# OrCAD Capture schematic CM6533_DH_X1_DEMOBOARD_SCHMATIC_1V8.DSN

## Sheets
1 00. Note: title: Note; rev: 1.8; company: C-MEDIA ELECTRONICS Inc.; note: CM6533_DH_X1_DEMOBOARD_SCHMATIC; note: 6F., 100, Sec. 4, Civil Boulevard, Taipei, Taiwan, R.O.C.
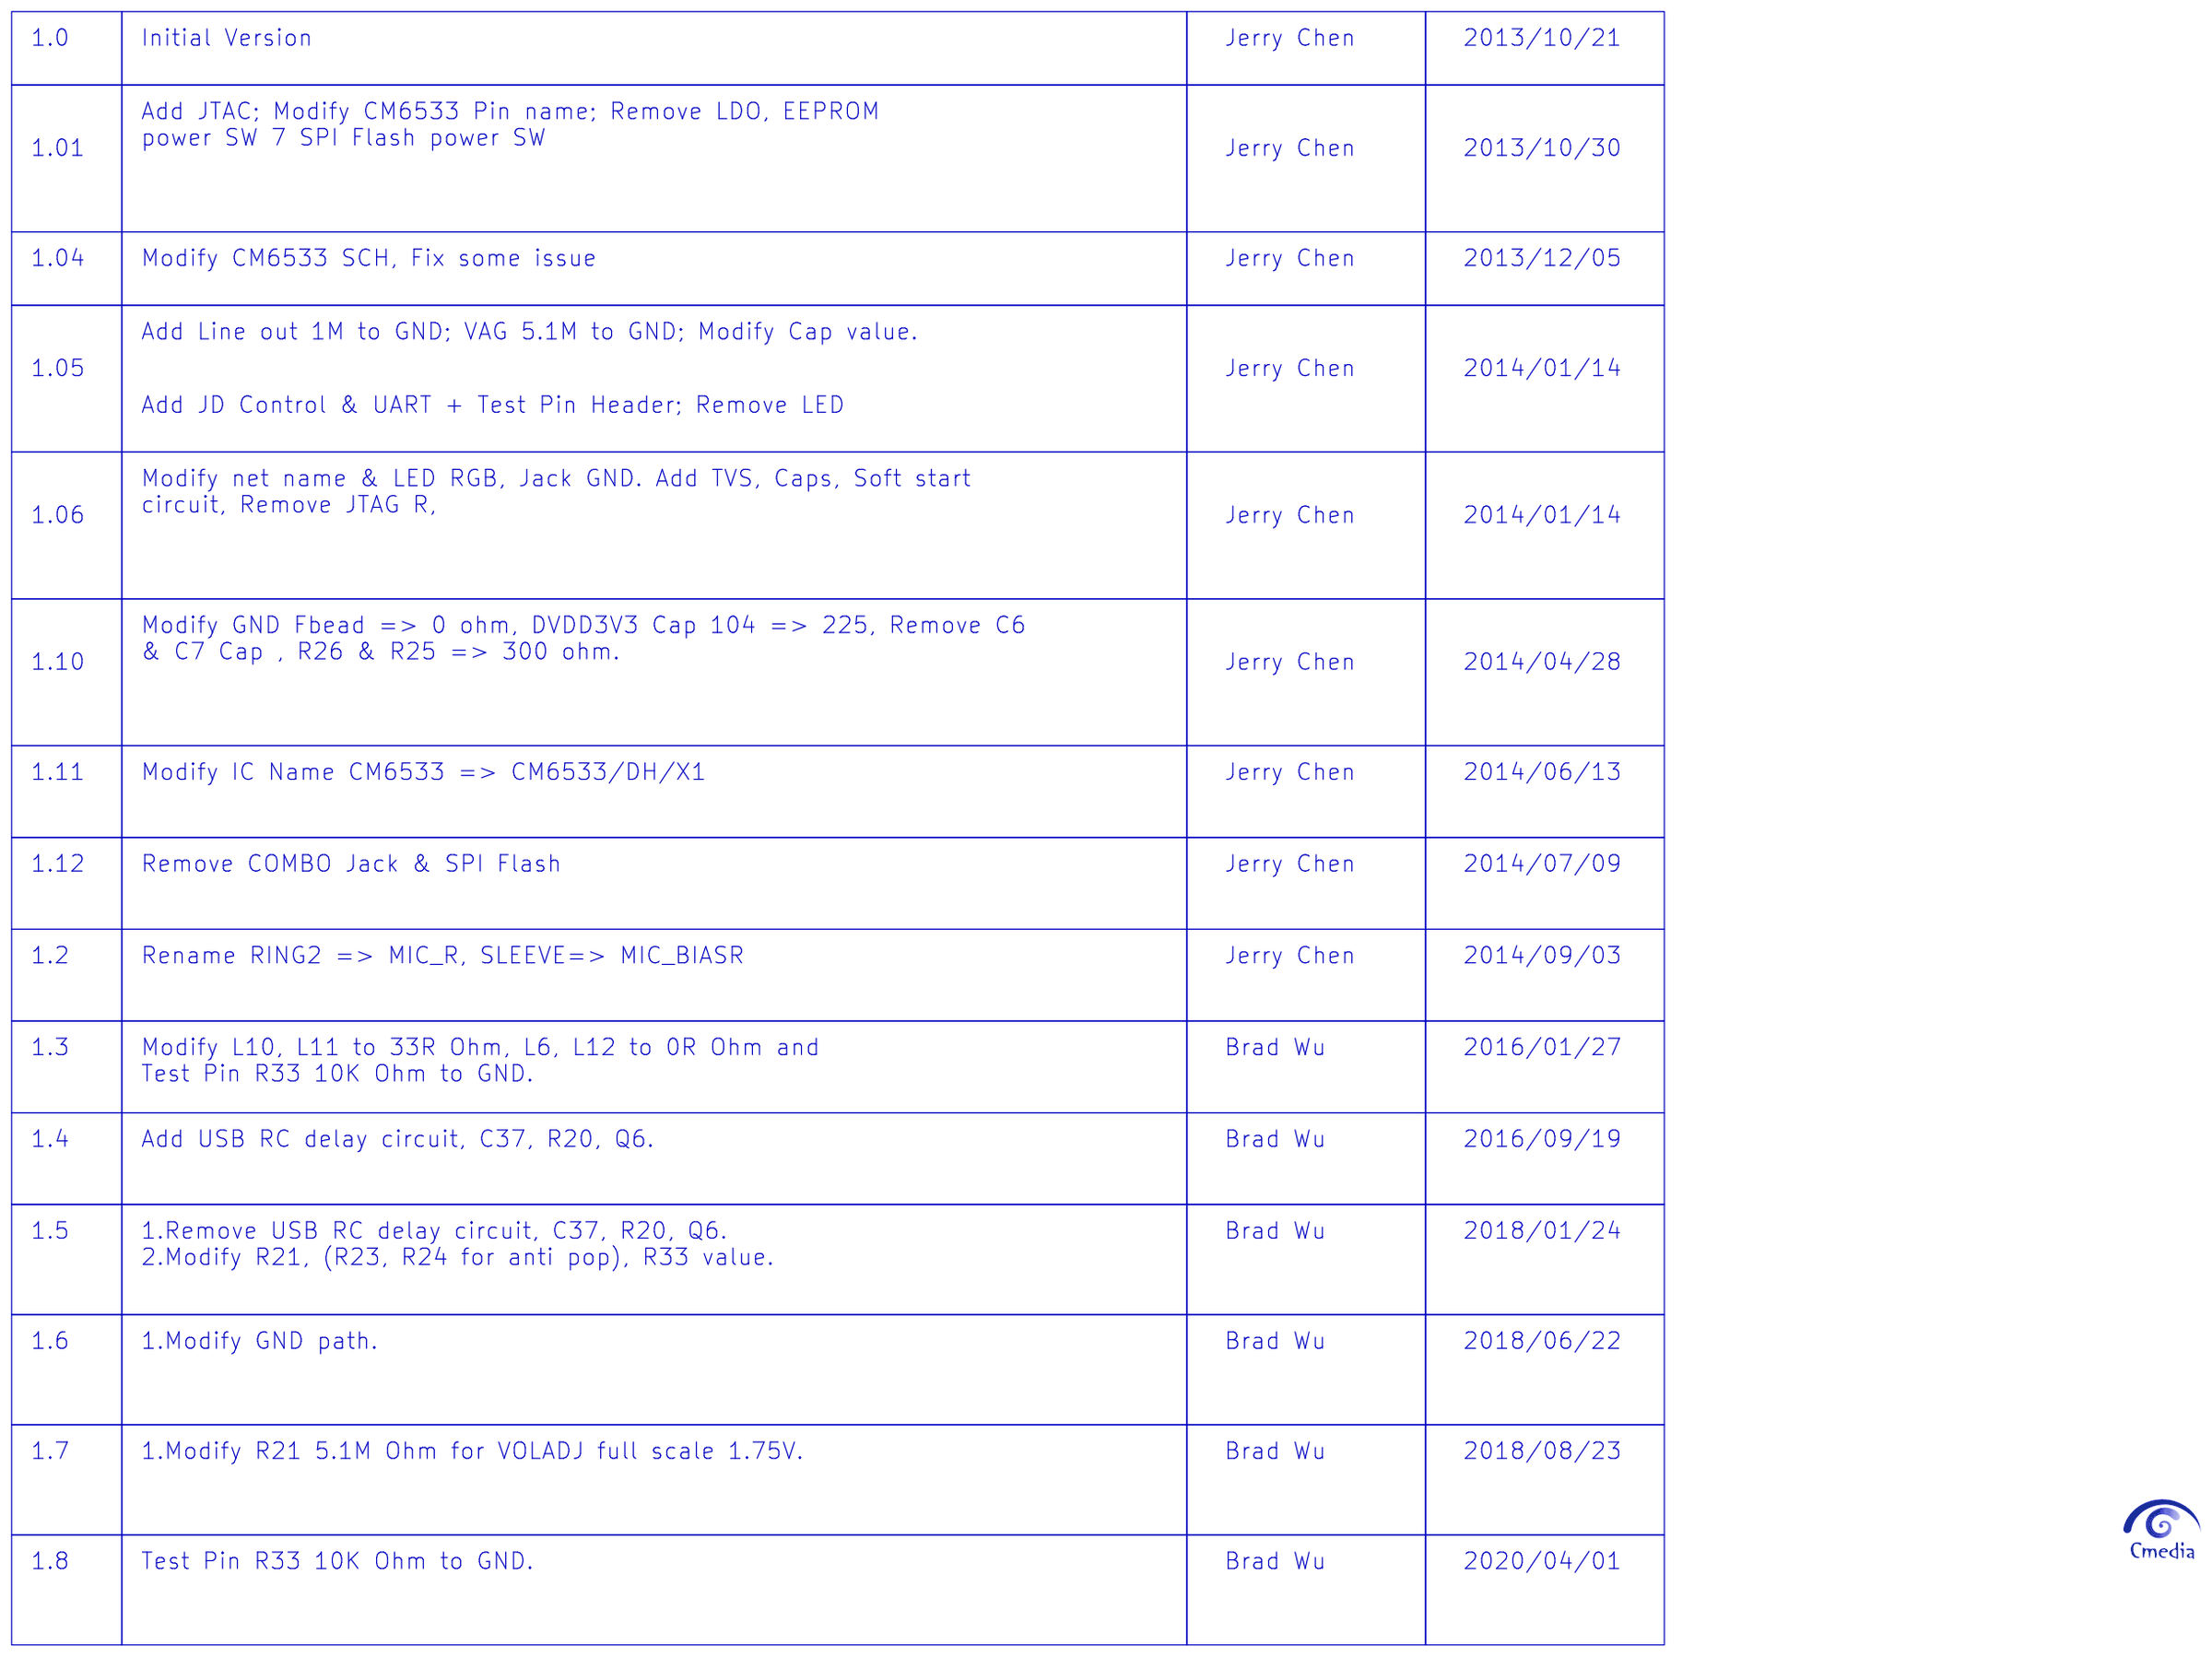
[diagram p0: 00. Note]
2 01. Placement: title: Placement
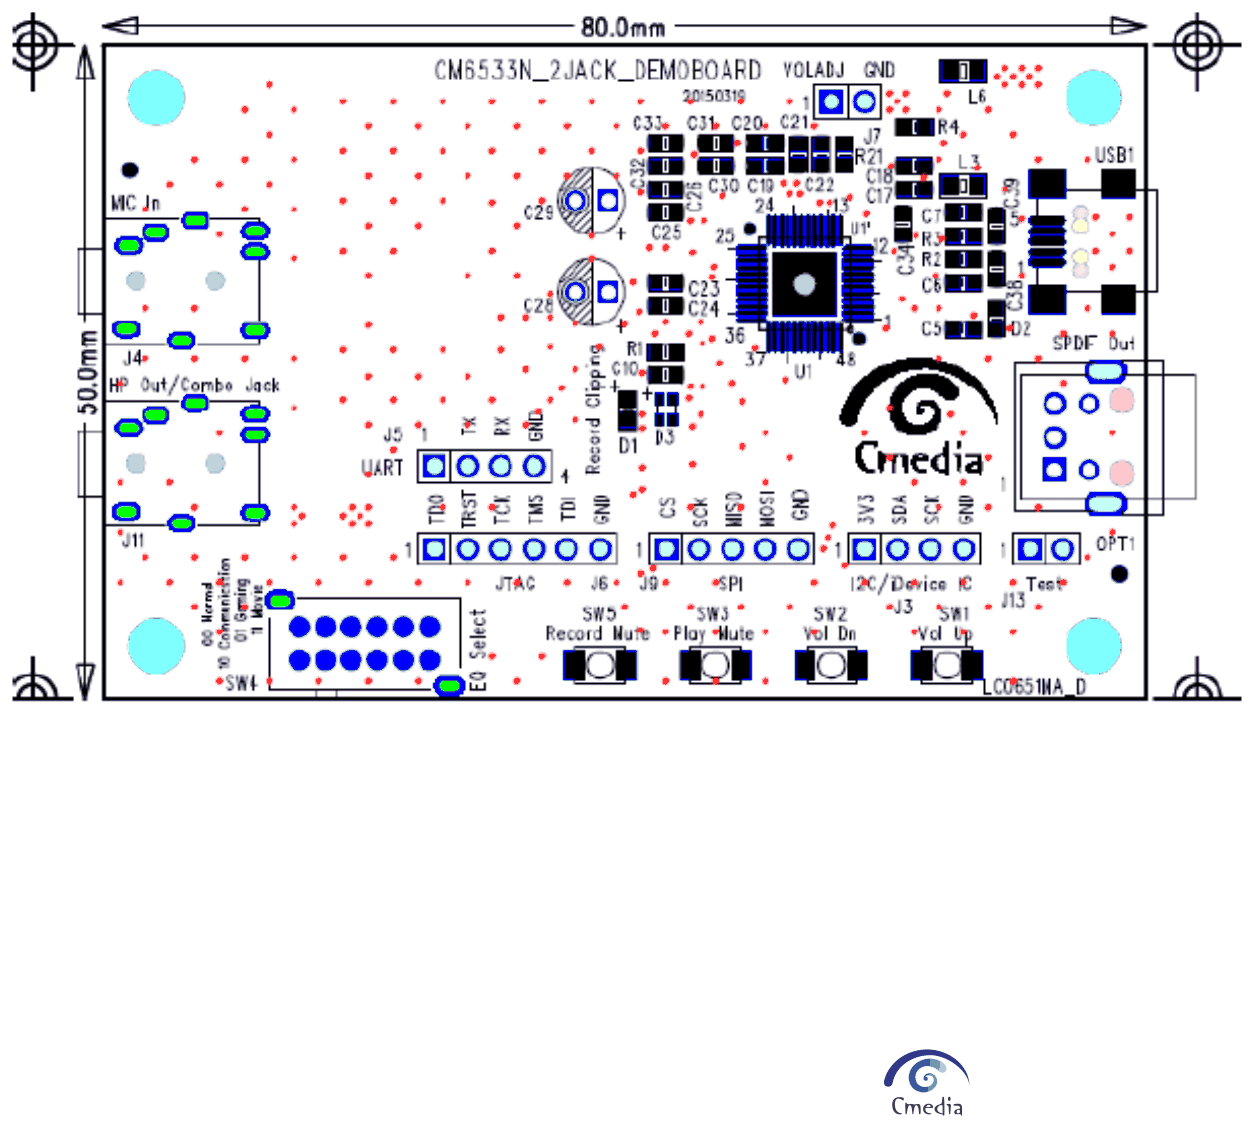
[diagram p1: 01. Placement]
3 02. Block: title: BLOCK
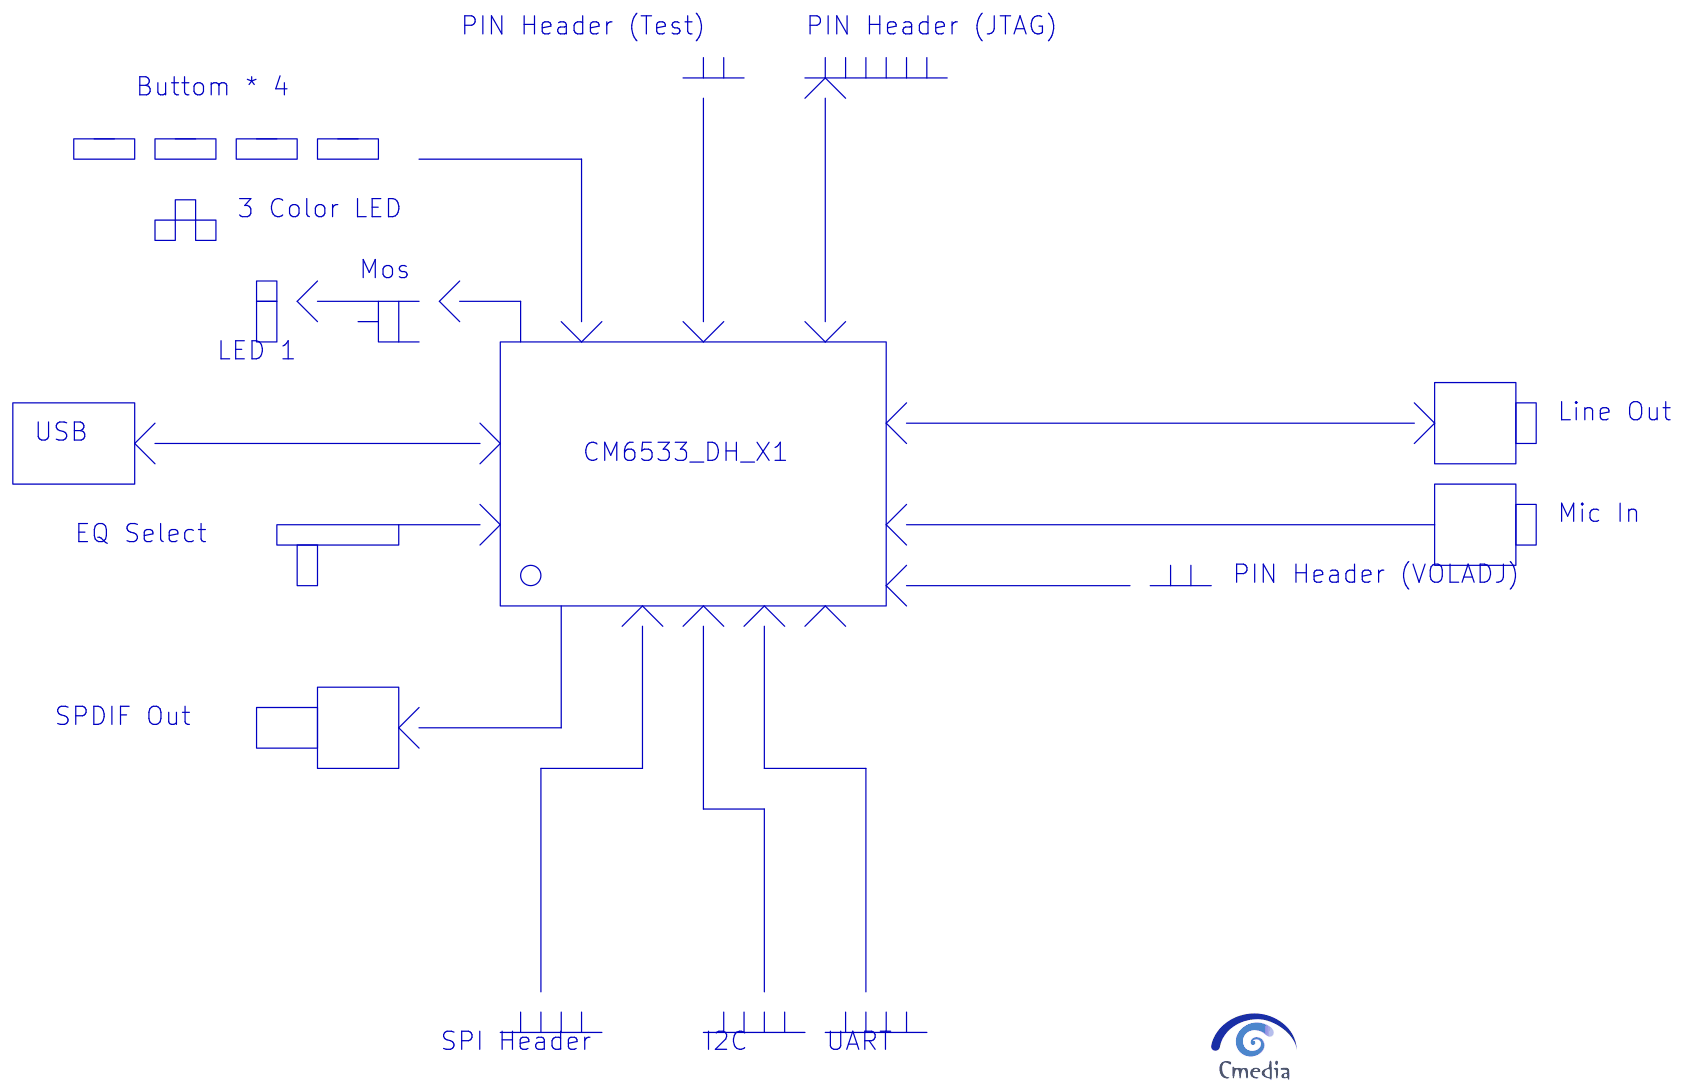
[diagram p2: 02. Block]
4 03. CM6533 Main: size B; title: CM6533/DH/X1 Demoboard
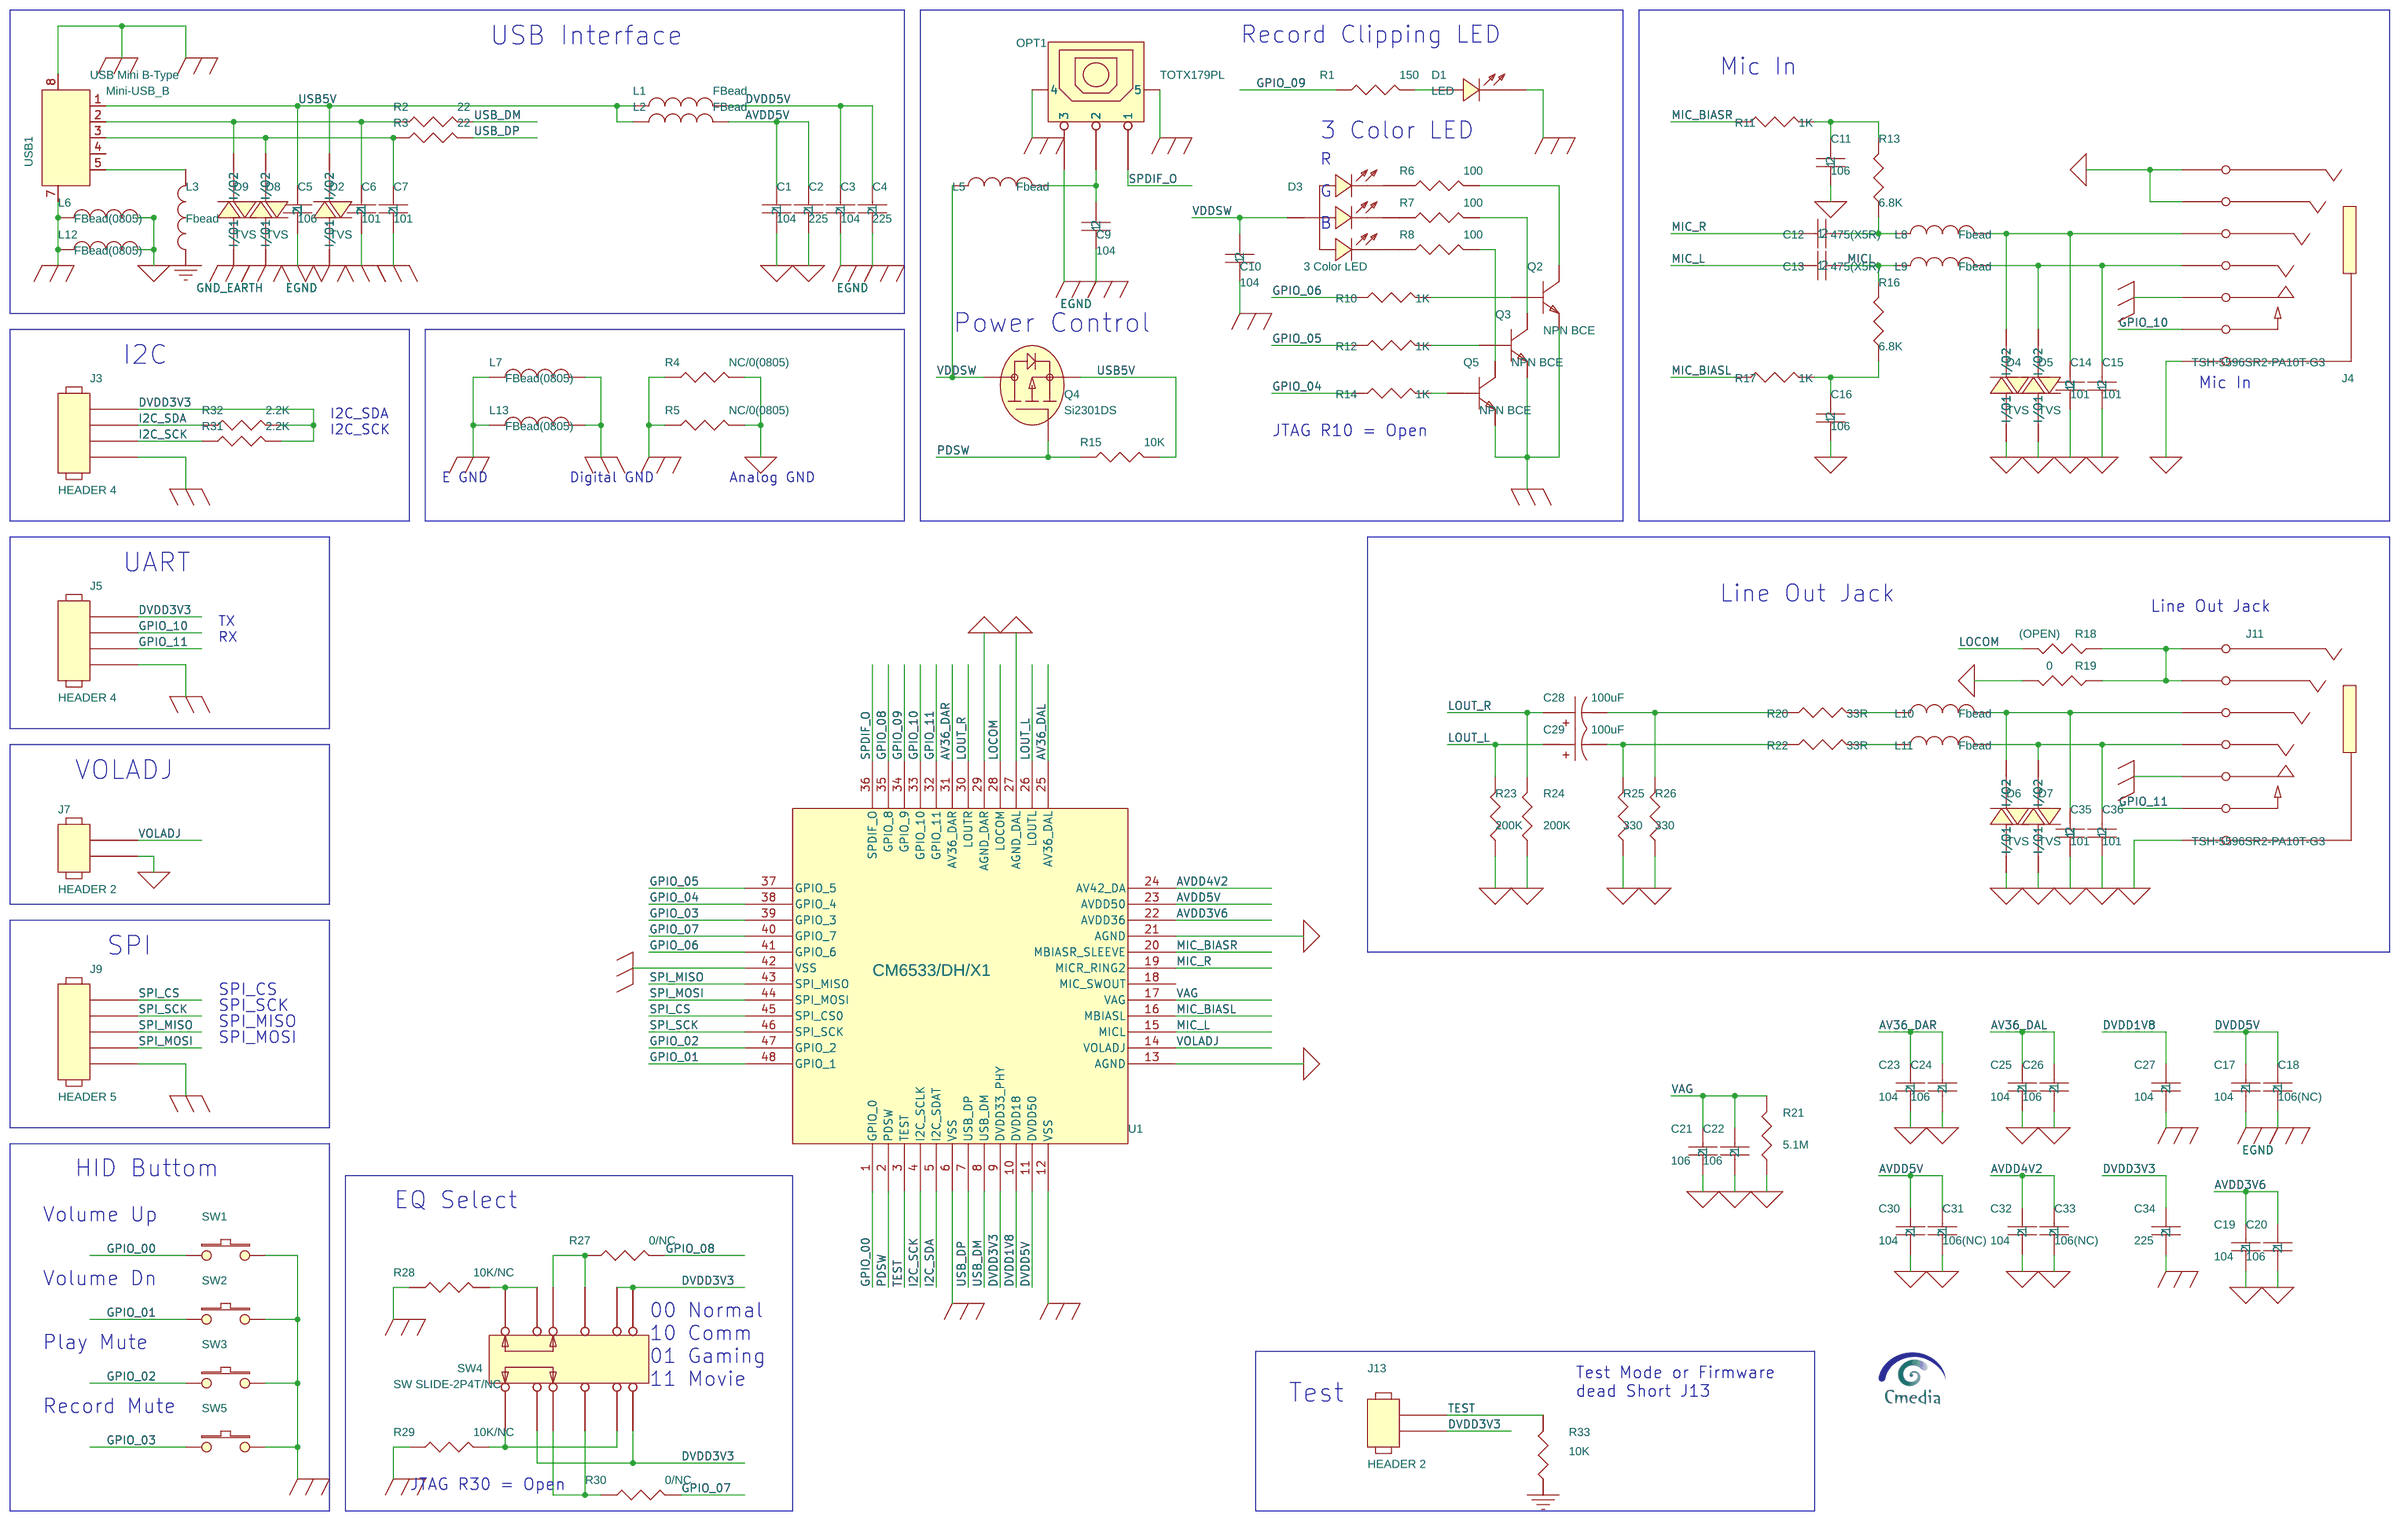
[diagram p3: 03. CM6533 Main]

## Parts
C1  104
C2  225
C3  104
C4  225
C5  106
C6  101
C7  101
C9  104
C10  104  [SM/C_0603]
C11  106
C12  475(X5R)
C13  475(X5R)
C14  101
C15  101
C16  106
C17  104
C18  106(NC)
C19  104
C20  106
C21  106
C22  106
C23  104
C24  106
C25  104
C26  106
C27  104
C28  100uF
C29  100uF
C30  104
C31  106(NC)
C32  104
C33  106(NC)
C34  225
C35  101
C36  101
D1  LED
D2  TVS
D3  3 Color LED
D4  TVS
D5  TVS
D6  TVS
D7  TVS
D8  TVS
D9  TVS
J3  HEADER 4
J4  TSH-5596SR2-PA10T-G3  [DIP]
J5  HEADER 4
J7  HEADER 2
J9  HEADER 5
J11  TSH-5596SR2-PA10T-G3  [DIP]
J13  HEADER 2
L1  FBead
L2  FBead
L3  Fbead
L5  Fbead
L6  FBead(0805)  [L0805]
L7  FBead(0805)  [L0805]
L8  Fbead
L9  Fbead
L10  Fbead
L11  Fbead
L12  FBead(0805)  [L0805]
L13  FBead(0805)  [L0805]
OPT1  TOTX179PL
Q2  NPN BCE
Q3  NPN BCE
Q4  Si2301DS  [SOT23]
Q5  NPN BCE
R1  150
R2  22
R3  22
R4  NC/0(0805)
R5  NC/0(0805)
R6  100  [R0603]
R7  100  [R0603]
R8  100  [R0603]
R10  1K
R11  1K
R12  1K
R13  6.8K
R14  1K
R15  10K  [R0603]
R16  6.8K
R17  1K
R18  (OPEN)
R19  0
R20  33R
R21  5.1M
R22  33R
R23  200K
R24  200K
R25  330
R26  330
R27  0/NC
R28  10K/NC
R29  10K/NC
R30  0/NC
R31  2.2K
R32  2.2K
R33  10K  [R0603]
SW1  CTT-1135  [TACKSW2-150]
SW2  CTT-1135  [TACKSW2-150]
SW3  CTT-1135  [TACKSW2-150]
SW4  SW SLIDE-2P4T/NC
SW5  CTT-1135  [TACKSW2-150]
U1  CM6533/DH/X1
USB1  Mini-USB_B  [USB-TYPEB-SMD]

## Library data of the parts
C1 = CAP_NP_13
C2 = CAP_NP_7
C3 = CAP_NP_11
C4 = CAP_NP_30
C5 = CAP_NP_15
C6 = CAP_NP_27
C7 = CAP_NP_9
C9 = CAP_NP_19
C10 = CAP_NP_5
C11 = CAP_NP_24
C12 = CAP_NP_18
C13 = CAP_NP_26
C14 = CAP_NP_16
C15 = CAP_NP
C16 = CAP_NP_17
C17 = CAP_NP_12
C18 = CAP_NP_28
C19 = CAP_NP_22
C20 = CAP_NP_6
C21 = CAP_NP_23
C22 = CAP_NP_25
C23 = CAP_NP_29
C24 = CAP_NP_14
C25 = CAP_NP_8
C26 = CAP_NP_31
C27 = CAP_NP_3
C28 C29 = CAPACITOR_POL
C30 = CAP_NP_20
C31 = CAP_NP_1
C32 = CAP_NP_21
C33 = CAP_NP_2
C34 = CAP_NP_4
C35 = CAP_NP_32
C36 = CAP_NP_10
D1 = LED
D2 D4-D9 = DA108S1_SO_2
D3 = LED_3
J3 J5 = HEADER_5_3
J4 J11 = PHONEJACK_STEREO_SW_15
J7 J13 = HEADER_5_5
J9 = HEADER_5_7
L1 = INDUCTOR_9
L2 = INDUCTOR_10
L3 = INDUCTOR_6
L5 = INDUCTOR_7
L6 = INDUCTOR_1
L7 = INDUCTOR_2
L8 = INDUCTOR
L9 = INDUCTOR_5
L10 = INDUCTOR_8
L11 = INDUCTOR_3
L12 = INDUCTOR_11
L13 = INDUCTOR_4
OPT1 = HEADER_3_2: 1ST PART FIELD: TOTX178
Q2 Q3 Q5 = NPN_BCE
Q4 = PWRMOSFET_EP_GSD_2
R1-R8 R10-R33 = R
SW1-SW3 SW5 = SW_PUSHBUTTON: 1ST PART FIELD: WAKE UP
SW4 = SW_SLIDE-4P2T_0
U1 = CMI120_22
USB1 = HEADER_4_2: 1ST PART FIELD: USB Mini B-Type

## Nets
AGND: C1.2 C2.2 C11.1 C14.1 C15.1 C16.1 C19.2 C20.2 C21.2 C22.2 C23.2 C24.2 C25.2 C26.2 C30.2 C31.2 C32.2 C33.2 C35.1 C36.1 D4.1(I/O1) D5.1(I/O1) D6.1(I/O1) D7.1(I/O1) J4.3 J4.4 J4.7 J7.2 J11.7 L6.2 L12.2 R4.2 R5.2 R19.1 R21.1 R23.1 R24.1 R25.1 R26.1 U1.13(AGND) U1.21(AGND) U1.27(AGND_DAL) U1.29(AGND_DAR)
AV36_DAL: C25.1 C26.1 U1.25(AV36_DAL)
AV36_DAR: C23.1 C24.1 U1.31(AV36_DAR)
AVDD3V6: C19.1 C20.1 U1.22(AVDD36)
AVDD4V2: C32.1 C33.1 U1.24(AV42_DA)
AVDD5V: C1.1 C2.1 C30.1 C31.1 L2.2 U1.23(AVDD50)
DGND: C3.2 C4.2 C5.2 C6.2 C7.2 C9.1 C10.1 C17.2 C18.2 C27.2 C34.2 D1.2(CATHODE) D2.1(I/O1) D8.1(I/O1) D9.1(I/O1) J3.4 J4.5 J5.4 J9.5 J11.5 L3.1 L6.1 L7.1 L7.2 L12.1 L13.1 L13.2 OPT1.3 OPT1.4 OPT1.5 Q2.3(E) Q3.3(E) Q5.3(E) R4.1 R5.1 R28.1 R29.1 R33.1 SW1.1 SW2.1 SW3.1 SW5.1 U1.6(VSS) U1.12(VSS) U1.42(VSS) USB1.7 USB1.8
DVDD1V8: C27.1 U1.10(DVDD18)
DVDD3V3: C34.1 J3.1 J5.1 J13.2 R31.2 R32.2 SW4.2 SW4.6 SW4.7 SW4.8 U1.9(DVDD33_PHY)
DVDD5V: C3.1 C4.1 C17.1 C18.1 L1.2 U1.11(DVDD50)
VDDSW: C10.2 D3.4(G) L5.1 Q4.3(DRAIN)
GPIO_00: SW1.2 U1.1(GPIO_0)
GPIO_01: SW2.2 U1.48(GPIO_1)
GPIO_02: SW3.2 U1.47(GPIO_2)
GPIO_03: SW5.2 U1.39(GPIO_3)
GPIO_04: R14.1 U1.38(GPIO_4)
GPIO_05: R12.1 U1.37(GPIO_5)
GPIO_06: R10.1 U1.41(GPIO_6)
GPIO_07: R30.2 U1.40(GPIO_7)
GPIO_08: R27.2 U1.35(GPIO_8)
GPIO_09: R1.1 U1.34(GPIO_9)
GPIO_10: J4.6 J5.2 U1.33(GPIO_10)
GPIO_11: J5.3 J11.6 U1.32(GPIO_11)
I2C_SCK: J3.3 R31.1 U1.4(I2C_SCLK)
I2C_SDA: J3.2 R32.1 U1.5(I2C_SDAT)
LOCOM: R18.1 U1.28(LOCOM)
LOUT_L: C29.1 R23.2 U1.26(LOUTL)
LOUT_R: C28.1 R24.2 U1.30(LOUTR)
MIC_BIASL: R17.2 U1.16(MBIASL)
MIC_BIASR: R11.2 U1.20(MBIASR_SLEEVE)
MIC_L: C13.1 U1.15(MICL)
MIC_R: C12.1 U1.19(MICR_RING2)
MICL: C13.2 L9.1 R16.1
PDSW: Q4.1(GATE) R15.1 U1.2(PDSW)
SPDIF_O: OPT1.1 U1.36(SPDIF_O)
SPI_CS: J9.1 U1.45(SPI_CS0)
SPI_MISO: J9.3 U1.43(SPI_MISO)
SPI_MOSI: J9.4 U1.44(SPI_MOSI)
SPI_SCK: J9.2 U1.46(SPI_SCK)
TEST: J13.1 R33.2 U1.3(TEST)
USB5V: C5.1 D2.2(I/O2) L1.1 L2.1 Q4.2(SOURCE) R15.2 USB1.1
USB_DM: R2.2 U1.8(USB_DM)
USB_DP: R3.2 U1.7(USB_DP)
VAG: C21.1 C22.1 R21.2 U1.17(VAG)
VOLADJ: J7.1 U1.14(VOLADJ)
N21486862: C6.1 D9.2(I/O2) R2.1 USB1.2
N21486934: C7.1 D8.2(I/O2) R3.1 USB1.3
N24851205: C29.2 R22.1 R25.2
N24851207: C35.2 D6.2(I/O2) J11.2 L10.2
N24851209: C36.2 D7.2(I/O2) J11.1 L11.2
N24851236: C28.2 R20.1 R26.2
N25083652: L3.2 USB1.5
N25215463: C12.2 L8.1 R13.2
N25215500: C16.2 R16.2 R17.1
N25215541: C11.2 R11.1 R13.1
N25215543: C14.2 D4.2(I/O2) J4.2 L8.2
N25215567: C15.2 D5.2(I/O2) J4.1 L9.2
N25303998: Q5.2(C) R8.2
N25304014: Q2.2(C) R6.2
N25304016: Q3.2(C) R7.2
N25304063: Q5.1(B) R14.2
N25304079: Q3.1(B) R12.2
N25304081: Q2.1(B) R10.2
N25310264: D1.1(ANODE) R1.2
N25897715: J11.3 J11.4 R18.2 R19.2
N25943131: R30.1 SW4.3 SW4.4
N25943133: R28.2 SW4.11 SW4.12
N25943135: R27.1 SW4.9 SW4.10
N25943137: R29.2 SW4.1 SW4.5
N26002541: L11.1 R22.2
N26002956: L10.1 R20.2
N26011915: C9.2 L5.2 OPT1.2
N26067465: D3.1(R) R6.1
N26067466: D3.3(B) R8.1
N26067467: D3.2(G) R7.1

Not connected (* = marked no-connect by the designer): U1 18(MIC_SWOUT); USB1 4

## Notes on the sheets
sheet 1
- 1.0
- Initial Version
- Jerry Chen
- 2013/10/21
- Add JTAC; Modify CM6533 Pin name; Remove LDO, EEPROM
  power SW 7 SPI Flash power SW
- 1.01
- Jerry Chen
- 2013/10/30
- 1.04
- Modify CM6533 SCH, Fix some issue
- Jerry Chen
- 2013/12/05
- Add Line out 1M to GND; VAG 5.1M to GND; Modify Cap value.
- 1.05
- Jerry Chen
- 2014/01/14
- Add JD Control & UART + Test Pin Header; Remove LED
- Modify net name & LED RGB, Jack GND. Add TVS, Caps, Soft start
  circuit, Remove JTAG R,
- 1.06
- Jerry Chen
- 2014/01/14
- Modify GND Fbead => 0 ohm, DVDD3V3 Cap 104 => 225, Remove C6
  & C7 Cap , R26 & R25 => 300 ohm.
- 1.10
- Jerry Chen
- 2014/04/28
- 1.11
- Modify IC Name CM6533 => CM6533/DH/X1
- Jerry Chen
- 2014/06/13
- 1.12
- Remove COMBO Jack & SPI Flash
- Jerry Chen
- 2014/07/09
- 1.2
- Rename RING2 => MIC_R, SLEEVE=> MIC_BIASR
- Jerry Chen
- 2014/09/03
- 1.3
- Modify L10, L11 to 33R Ohm, L6, L12 to 0R Ohm and
  Test Pin R33 10K Ohm to GND.
- Brad Wu
- 2016/01/27
- 1.4
- Add USB RC delay circuit, C37, R20, Q6.
- Brad Wu
- 2016/09/19
- 1.5
- 1.Remove USB RC delay circuit, C37, R20, Q6.
  2.Modify R21, (R23, R24 for anti pop), R33 value.
- Brad Wu
- 2018/01/24
- 1.6
- 1.Modify GND path.
- Brad Wu
- 2018/06/22
- 1.7
- 1.Modify R21 5.1M Ohm for VOLADJ full scale 1.75V.
- Brad Wu
- 2018/08/23
- 1.8
- Test Pin R33 10K Ohm to GND.
- Brad Wu
- 2020/04/01
sheet 3
- PIN Header (Test)
- PIN Header (JTAG)
- Buttom * 4
- 3 Color LED
- Mos
- LED 1
- USB
- Line Out
- CM6533_DH_X1
- Mic In
- EQ Select
- PIN Header (VOLADJ)
- SPDIF Out
- SPI Header
- I2C
- UART
sheet 4
- USB Interface
- Record Clipping LED
- Mic In
- 3 Color LED
- R
- G
- B
- Power Control
- I2C
- Mic In
- I2C_SDA
- I2C_SCK
- JTAG R10 = Open
- E GND
- Digital GND
- Analog GND
- UART
- Line Out Jack
- Line Out Jack
- TX
- RX
- VOLADJ
- SPI
- SPI_CS
- SPI_MISO
- SPI_SCK
- SPI_MOSI
- HID Buttom
- EQ Select
- Volume Up
- Volume Dn
- 00 Normal
  10 Comm
  01 Gaming
  11 Movie
- Play Mute
- Test Mode or Firmware
  dead Short J13
- Test
- Record Mute
- JTAG R30 = Open
